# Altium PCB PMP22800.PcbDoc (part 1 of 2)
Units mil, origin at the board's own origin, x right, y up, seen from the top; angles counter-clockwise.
Board outline 4251.97 x 3450 mil, 2 copper layers (Top Layer, Bottom Layer), stack 62 mil thick; 97 components, 47 nets, 286 pads, 121 vias.
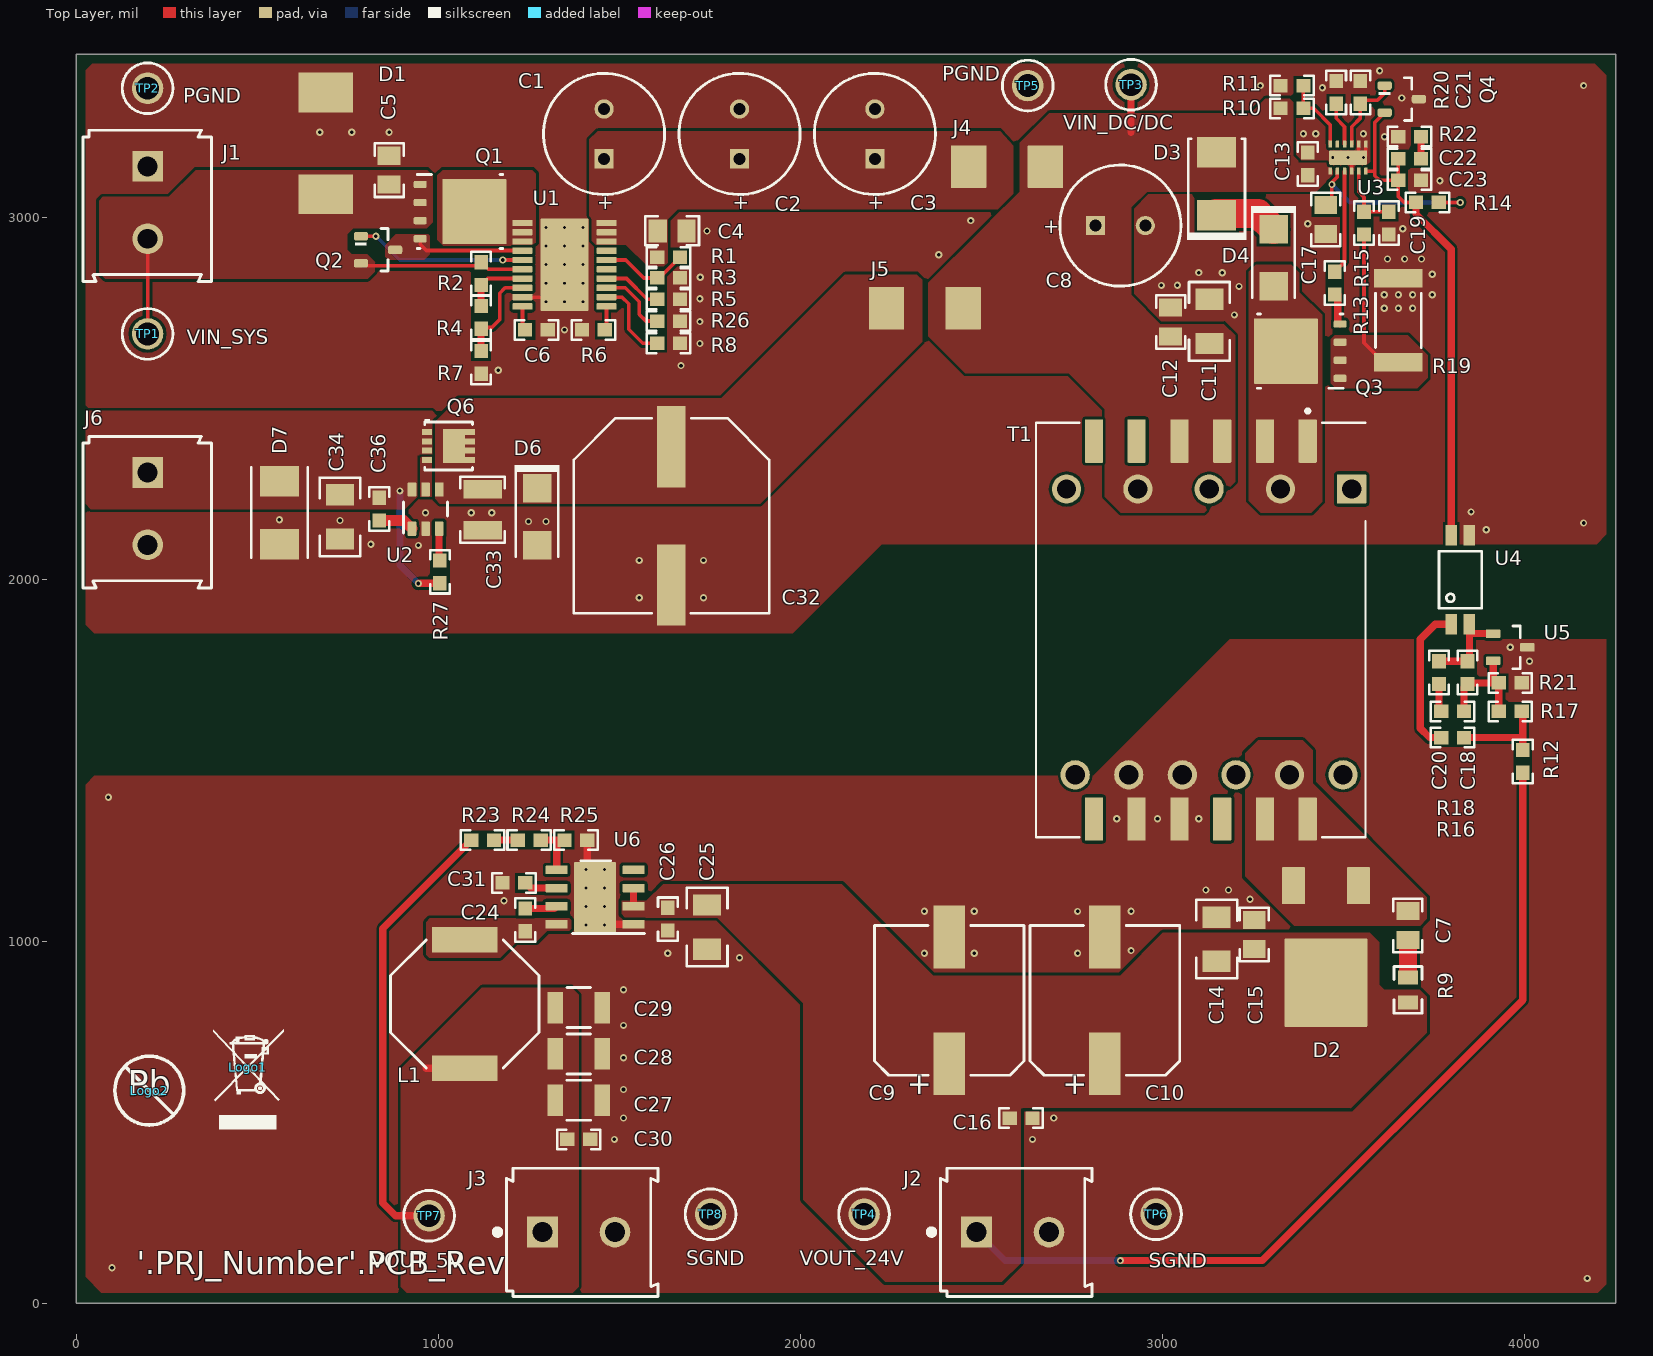
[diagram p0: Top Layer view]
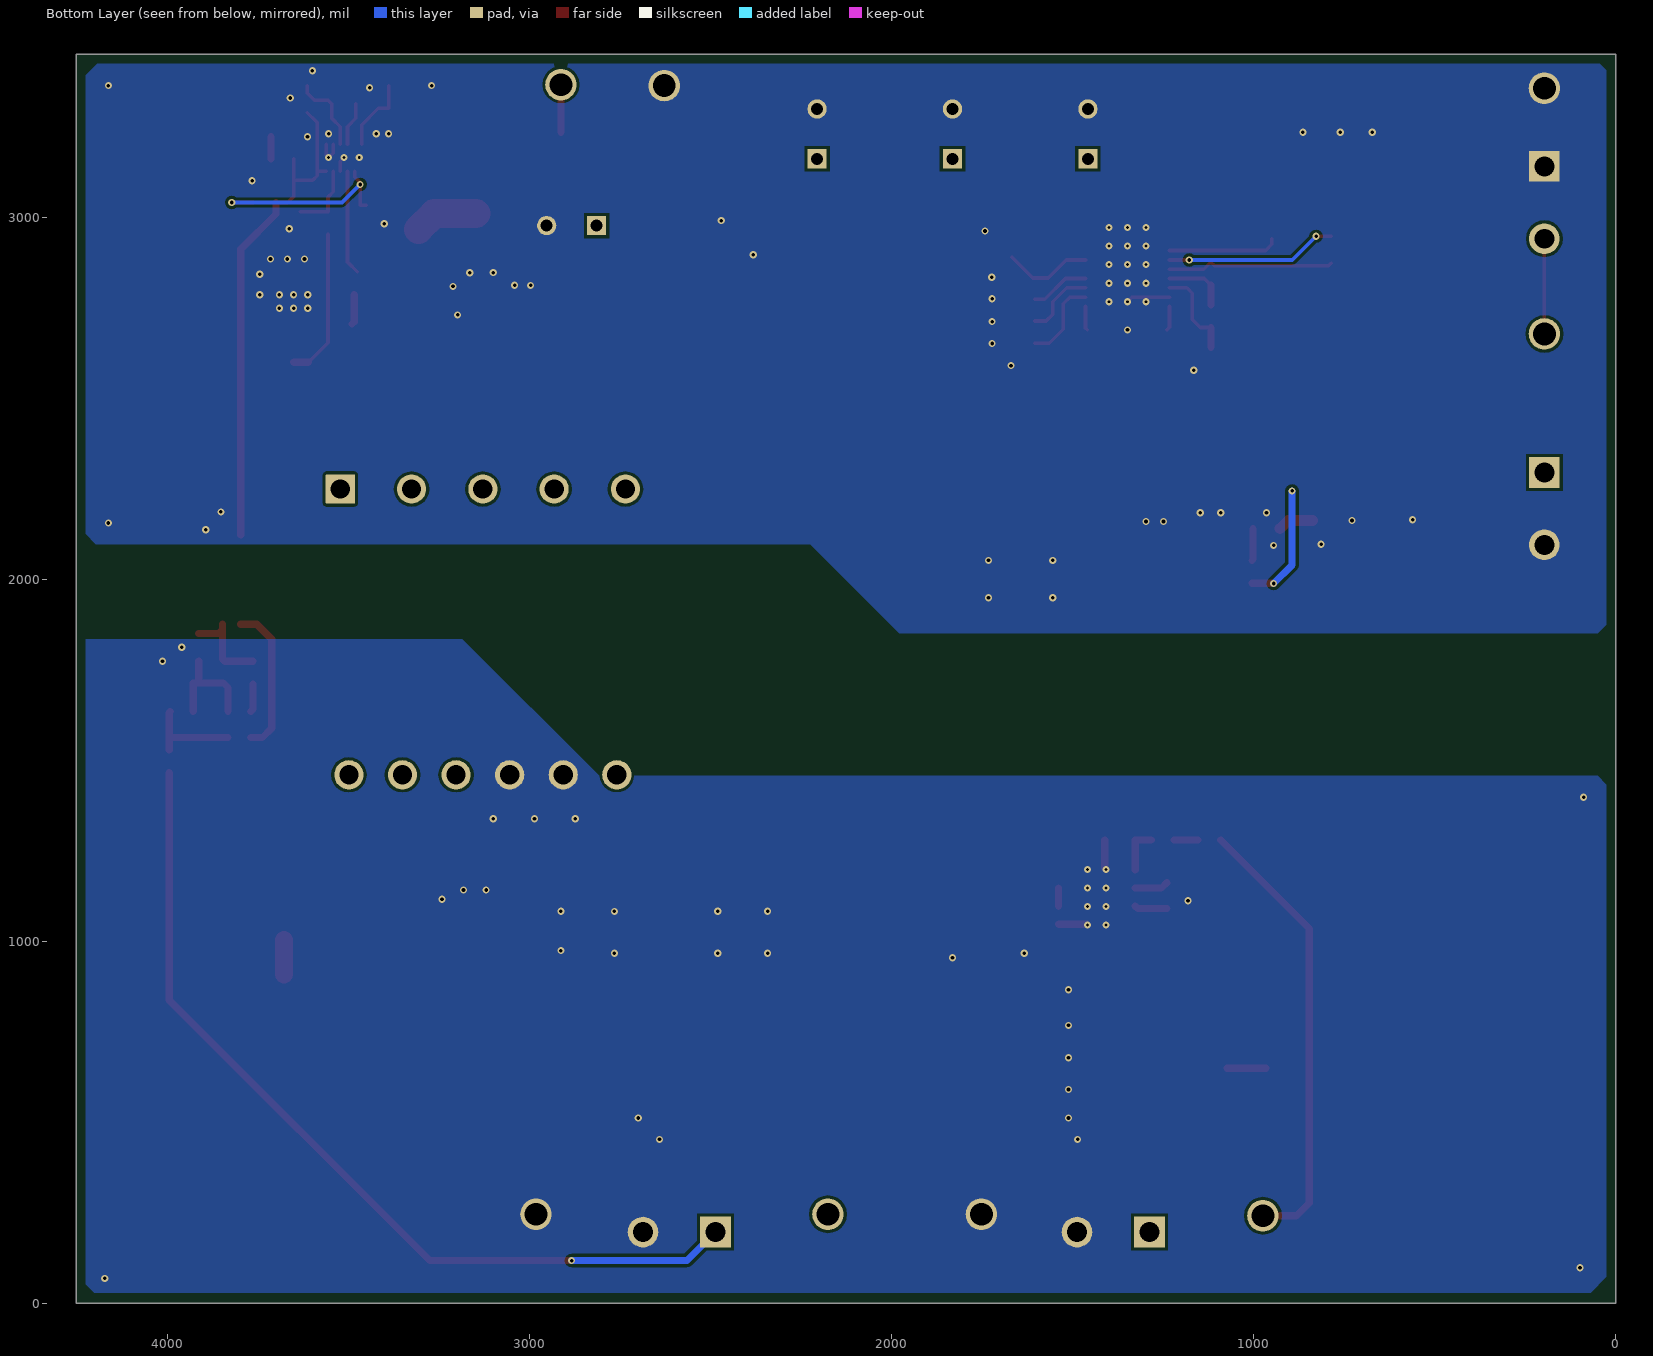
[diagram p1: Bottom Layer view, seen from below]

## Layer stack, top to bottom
Top Solder: solder mask 0.4, Solder Resist, Dk 3.5
Top Layer: signal copper 1.4
Dielectric1: core 59.2, FR-4, Dk 4.8
Bottom Layer: signal copper 1.4
Bottom Solder: solder mask 0.4, Solder Resist, Dk 3.5

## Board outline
0,0 4251.97,0 4251.97,3450 0,3450

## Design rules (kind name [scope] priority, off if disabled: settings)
AcuteAngle [All] p1: minimum=4.50000000000000E+0001 checktracksonly=FALSE
AssemblyTestPointUsage [All] p1: valid=2
BoardOutlineClearance BoardOutlineClearance_MountingHoles [OnCopper and InComponentClass('Mounting Holes')] p1: gap=25 ignorepadtopadclearanceinfootprint=FALSE
BoardOutlineClearance BoardOutlineClearance_Poly [OnCopper and InPoly] p2: gap=25 ignorepadtopadclearanceinfootprint=FALSE
BoardOutlineClearance [OnCopper and Not InComponentClass('Logo') and not InComponentClass('FiducialMark') and not InRegion(1000,500,4000,800)] p3: gap=25 ignorepadtopadclearanceinfootprint=FALSE
Clearance Clearance_Keepouts [((IsTrack Or IsArc) And Not InPoly) And IsFree and IsKeepOut vs ((IsTrack Or IsArc) And Not InPoly) And IsFree and IsKeepOut] p1: gap=0 ignorepadtopadclearanceinfootprint=FALSE
Clearance Clearance_Poly [InPolygon] p2: gap=8 ignorepadtopadclearanceinfootprint=FALSE except(0: Arc-Hole Track-Hole SMDPad-Hole THPad-Hole Via-Hole Fill-Hole Poly-Hole Region-Hole Text-Hole)
Clearance Clearance_FiducialMark [IsKeepOut and InComponentClass('FiducialMark') vs IsPad and InComponentClass('FiducialMark')] p3: gap=0 ignorepadtopadclearanceinfootprint=FALSE
Clearance [All] p4: gap=7.87 ignorepadtopadclearanceinfootprint=FALSE except(0: Arc-Hole Track-Hole SMDPad-Hole THPad-Hole Via-Hole Fill-Hole Poly-Hole Region-Hole Text-Hole)
ComponentClearance ComponentClearance_MountingHoles_FiducialMarks [InComponentClass('Mounting Holes') vs InComponentClass('FiducialMark')] p1: gap=50 collisioncheckmode=3 verticalgap=10 showdistances=FALSE
ComponentClearance ComponentClearance_Shunt [InComponentClass('Header') vs InComponentClass('Shunt')] p2: gap=0 collisioncheckmode=3 verticalgap=0 showdistances=FALSE
ComponentClearance ComponentClearance_Logo [InComponentClass('Logo')] p3: gap=50 collisioncheckmode=3 verticalgap=10 showdistances=FALSE
ComponentClearance ComponentClearance_ScrewToNut [(HasFootprint('NY PMS 440 0025 PH')) vs (HasFootprint('Keystone_1902C'))] p4: gap=5 collisioncheckmode=3 verticalgap=10 showdistances=FALSE
ComponentClearance ComponentClearance_MountingHoles [InComponentClass('Mounting Holes')] p5: gap=250 collisioncheckmode=3 verticalgap=100000 showdistances=FALSE
ComponentClearance ComponentClearance_SmallPassives [HasFootprint('0201*') or HasFootprint('0402*') or HasFootprint('0508') or HasFootprint('0603*') or HasFootprint('0612') or HasFootprint('0805*') or HasFootprint('0815*') or HasFootprint('0830*') or HasFootprint('1206*') or HasFootprint('1210*') or HasFootprint('1808*') or HasFootprint('1812*') or HasFootprint('1825*') or HasFootprint('2010*') or HasFootprint('2220*') or HasFootprint('2225*') or HasFootprint('2512*') or HasFootprint('2728*') or HasFootprint('3518*') vs HasFootprint('0201*') or HasFootprint('0402*') or HasFootprint('0508') or HasFootprint('0603*') or HasFootprint('0612') or HasFootprint('0805*') or HasFootprint('0815*') or HasFootprint('0830*') or HasFootprint('1206*') or HasFootprint('1210*') or HasFootprint('1808*') or HasFootprint('1812*') or HasFootprint('1825*') or HasFootprint('2010*') or HasFootprint('2220*') or HasFootprint('2225*') or HasFootprint('2512*') or HasFootprint('2728*') or HasFootprint('3518*')] p6: gap=14.96 collisioncheckmode=3 verticalgap=10 showdistances=FALSE
ComponentClearance ComponentClearance_THtoSMT [IsThruComponent vs IsSMTComponent] p7: gap=15 collisioncheckmode=3 verticalgap=30 showdistances=FALSE
ComponentClearance ComponentClearance_THtoTH [IsThruComponent vs IsThruComponent] p8: gap=15 collisioncheckmode=3 verticalgap=30 showdistances=FALSE
ComponentClearance [All] p9: gap=15 collisioncheckmode=3 verticalgap=10 showdistances=FALSE
DiffPairsRouting [All] p1: maxlimit=100 minlimit=10 mostfreqgap=10 toplayer_minwidth=15 toplayer_maxwidth=15 toplayer_prefwidth=15 bottomlayer_minwidth=15 bottomlayer_maxwidth=15 bottomlayer_prefwidth=15 maxuncoupledlength=1000
FabricationTestPointUsage TestPointUsage [All] p1: valid=2 allowmultiple=FALSE
FabricationTestpoint Testpoint [All] p1: side=3 testpointundercomponent=TRUE minsize=40 maxsize=100 preferedsize=60 minholesize=0 maxholesize=40 preferedholesize=32 testpointgrid=1 allowsidetop=TRUE allowsidebottom=TRUE usegrid=TRUE gridtolerance=0.01
FanoutControl Fanout_LCC [IsLCC] p1: bgadir=Out bgaviamode=Centered fanoutstyle=Auto fanoutdirection=Alternating viagrid=1 // Fanout_LCC (Default Rule)
FanoutControl Fanout_BGA [IsBGA] p2: bgadir=Out bgaviamode=Centered fanoutstyle=Auto fanoutdirection=Alternating viagrid=1 // Fanout_BGA (Default Rule)
FanoutControl Fanout_Default [All] p4: bgadir=Out bgaviamode=Centered fanoutstyle=Auto fanoutdirection=Alternating viagrid=1 // Fanout_Default (Default Rule)
FanoutControl Fanout_Small [(CompPinCount < 5)] p5: bgadir=Out bgaviamode=Centered fanoutstyle=Auto fanoutdirection=OutThenIn viagrid=1 // Fanout_Small (Default Rule)
HoleSize [All] p1: absolutevalues=TRUE maxlimit=251 minlimit=7.87 maxpercent=80.000 minpercent=20.000
MinimumAnnularRing MinimumAnnularRing_ThermalPadVias [IsVia and InAnyComponent] p1: minimumring=5
MinimumAnnularRing [All] p2: minimumring=5
MinimumSolderMaskSliver MinimumSolderMaskSliver_Logo [InComponentClass('Logo') vs InComponentClass('Logo')] p1: minsoldermaskwidth=0.7
MinimumSolderMaskSliver [All] p2: minsoldermaskwidth=3.94
PlaneConnect [All] p1: planeconnectstyle=Direct reliefexpansion=10 reliefentries=4 reliefconductorwidth=10 reliefairgap=10
PolygonConnect [All] p1: connectstyle=Direct reliefconductorwidth=10 reliefentries=4 polygonreliefangle="90 Angle" airgapwidth=10
RoutingVias ThermalPadVias [IsVia and InAnyComponent] p1: holewidth=7.87 width=19.68 viastyle="Through Hole" minholewidth=7.87 minwidth=19.68 maxholewidth=12.99 maxwidth=23.62
RoutingVias [All] p2: holewidth=16 width=34 viastyle="Through Hole" minholewidth=5 minwidth=10 maxholewidth=40 maxwidth=65
SilkToBoardRegionClearance [Not ((IsComment or IsDesignator) And (Hide <> 'False')) and not InRegion(1000,500,4000,800)] p1:
SilkToSilkClearance SilkToSilkClearance_Pb-FreeLogo [(HasFootprint('Pb-Free_Overlay_Medium') OR HasFootprint('Pb-Free_Overlay_Small')) vs (HasFootprint('Pb-Free_Overlay_Medium') OR HasFootprint('Pb-Free_Overlay_Small'))] p1: silktosilkclearance=0
SilkToSilkClearance [All] p2: silktosilkclearance=4
SilkToSolderMaskClearance SilkToComponentPadClearance [IsPad and InAnycomponent] p1: minsilkscreentomaskgap=5 clearancetoexposedcopper=TRUE
SilkToSolderMaskClearance "Silk to Solder Mask Opening" [All] p2: minsilkscreentomaskgap=4 clearancetoexposedcopper=FALSE
SolderMaskExpansion [All] p1: expansion=1.97
Width [All] p1: maxlimit=100 minlimit=6 preferedwidth=10 checkconnectedcopper=TRUE
15 further rules are at their usual default settings.

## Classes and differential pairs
component class PMP22800_Protection: !PCB1 C1 C2 C3 C4 C5 C6 C32 C33 C34 C36 D1 D6 D7 J1 J4 J5 J6 Logo1 Logo2 Q1 Q2 Q6 R1 R2 R3 R4 R5 R6 R7 R8 R26 R27 TP1 TP2 U1 U2
component class PMP22800_Power: C7 C8 C9 C10 C11 C12 C13 C14 C15 C16 C17 C18 C19 C20 C21 C22 C23 C24 C25 C26 C27 C28 C29 C30 C31 D2 D3 D4 J2 J3 L1 Q3 Q4 R9 R10 R11 R12 R13 R14 R15 R16 R17 R18 R19 R20 R21 R22 R23 R24 R25 T1 TP3 TP4 TP5 TP6 TP7 TP8 U3 U4 U5 U6

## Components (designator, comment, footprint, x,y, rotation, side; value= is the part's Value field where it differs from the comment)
C1 "EKZN350ELL221MH15D" KZN_800x1500 1457.77,3230.17 r90 top value=220uF
C2 "EKZN350ELL221MH15D" KZN_800x1500 1831.78,3230.17 r90 top value=220uF
C3 "EKZN350ELL221MH15D" KZN_800x1500 2205.8,3230.17 r90 top value=220uF
C4 "GJ821BR71H105KA12L" 0805_HV 1645.93,2962.24 r0 top value=1uF
C5 "GJ821BR71H105KA12L" 0805_HV 863.88,3129.92 r90 top value=1uF
C6 "C0603C223K3RACTU" 0603 1270.76,2688.83 r0 top value=0.022uF
C7 "C2012X7R2E102K085AA" 0805_HV 3678.15,1043.31 r90 top value=1000pF
C8 "EKZN350ELL221MH15D" KZN_800x1500 2883.86,2976.92 r0 top value=220uF
C9 "HHXB500ARA101MJA0G" HXB_JA0 2411.42,836.61 r90 top value=100uF
C10 "HHXB500ARA101MJA0G" HXB_JA0 2841.04,836.61 r90 top value=100uF
C11 "CL31B106KBHNNNE" 1206_180M 3129.92,2712.38 r90 top value=10uF
C12 "CL21B105KBFNFNE" 0805_HV 3022.72,2710.69 r90 top value=1uF
C13 "06035C104JAT2A" 0603 3401.38,3147.18 r90 top value=0.1uF
C14 "CL31B106KBHNNNE" 1206_180M 3149.61,1005.91 r90 top value=10uF
C15 "CL21B105KBFNFNE" 0805_HV 3253.67,1018.35 r90 top value=1uF
C16 "06035C104JAT2A" 0603 2609.68,511.81 r0 top value=0.1uF
C17 "C2012X7R1E475K125AB" 0805_HV 3451.25,2993.54 r90 top value=4.7uF
C18 "C0603C103K5RACTU" 0603 3842.72,1742.13 r90 top value=0.01uF
C19 "C0603C331K5RACTU" 0603 3625.68,2983.7 r90 top value=330pF
C20 "06035C104JAT2A" 0603 3763.98,1742.13 r90 top value=0.1uF
C21 "GRM188R71E103KA01D" 0603 3546.94,3344.98 r90 top value=0.01uF
C22 "C0603X104K3RACTU" 0603 3682.77,3161.72 r0 top value=0.1uF
C23 "C0603C331K5RACTU" 0603 3682.77,3102.66 r0 top value=330pF
C24 "C0603X104K3RACTU" 0603 1240.16,1059.06 r270 top value=0.1uF
C25 "C3216X7R1H475K160AE" 1206_190M 1742.13,1039.37 r270 top value=4.7uF
C26 "C1608X7R1H224K080AB" 0603 1633.86,1061.02 r270 top value=0.22uF
C27 "C3225X7R1C226K250AC" 1210_280 1387.8,561.02 r0 top value=22uF
C28 "C3225X7R1C226K250AC" 1210_280 1387.8,688.98 r0 top value=22uF
C29 "C3225X7R1C226K250AC" 1210_280 1387.8,816.93 r0 top value=22uF
C30 "C0603C104J4RACTU" 0603 1387.8,452.76 r180 top value=0.1uF
C31 "CL10B105KO8NFNC" 0603 1208.66,1161.42 r180 top value=1uF
C32 "EEV-FK1J221Q" SM_RADIAL_H13 1643.7,2175.2 r270 top value=220uF
C33 "C1210C225K1RACTU" 1210_210 1122.24,2191.93 r270 top value=2.2uF
C34 "CGA5L2X8R1H334K160AA" 1206_180M 728.35,2172.24 r270 top value=0.33uF
C36 "CGA3E1X7R1E105K080AD" 0603 836.61,2193.9 r270 top value=1uF
D1 "SMCJ33CA-13-F" SMC_Bi 688.98,3203.92 r270 top value=33V
D2 "VS-50WQ10FNTRHM3" DPAK 3451.77,1019.69 r270 top value=100V
D3 "SMBJ30A-13-F" SMB 3149.61,3092.22 r90 top value=30V
D4 "ES1C-13-F" SMA 3307.09,2887.73 r270 top value=150V
D6 "SMAJ58A" SMA 1272.64,2172.24 r270 top value=58V
D7 "SMBJ33CA-13-F" SMB-Bi 561.02,2184.06 r90 top value=33V
J1 "282841-2" TEC_282841-2 196.85,3040.61 r270 top
J2 "282841-2" TEC_282841-2 2586.61,196.85 r0 top
J3 "282841-2" TEC_282841-2 1387.8,196.85 r0 top
J4 "5102" Keystone_5102 2570.77,3139.57 r0 top
J5 "5102" Keystone_5102 2343.77,2748.82 r0 top
J6 "282841-2" TEC_282841-2 196.85,2194.88 r270 top
L1 "744066180" WE-TPC_1038 1072.83,826.77 r270 top value=18uH
Logo1 "WEEE logo" WEEE_Minimum 473.23,652.42 r0 top
Logo2 "Pb-Free Symbol" Pb-Free_Overlay_Medium 201.53,587.75 r0 top
Q1 "CSD19533Q5A" DQJ0008A 1059.84,3015.61 r0 top value=100V
Q2 "RK7002BMT116" SOT-23_Rohm 833.37,2910.1 r0 top value=60V
Q3 "CSD19533Q5A" DQJ0008A 3380.71,2629.92 r180 top value=100V
Q4 "FMMT718TA" SOT-23 3661.12,3326.28 r0 top value="20 V"
Q6 "DMT6007LFG-13" PowerDI3333-8 1028.2,2368.11 r0 top value=60V
R1 "RC0603FR-07499KL" 0603 1636.08,2889.86 r180 top value=499k
R2 "RC0603FR-07453KL" 0603 1118.11,2844.23 r90 top value=453k
R3 "RC0603FR-0782K5L" 0603 1636.08,2832.32 r180 top value=82.5k
R4 "RC0603FR-0760K4L" 0603 1118.11,2723.29 r90 top value=60.4k
R5 "RC0603FR-0722K6L" 0603 1636.08,2773.26 r0 top value=22.6k
R6 "RC0603FR-073K01L" 0603 1428.24,2688.83 r180 top value=3.01k
R7 "RC0603FR-0720KL" 0603 1118.11,2599.15 r90 top value=20.0k
R8 "RMCF0603ZT0R00" 0603 1636.08,2652.08 r180 top value=0
R9 "5106" 5106 3678.15,866.14 r270 top value=0
R10 "CRCW06031M40FKEA" 0603 3357.97,3300.69 r180 top value=1.40Meg
R11 "RC0603FR-07150KL" 0603 3357.97,3363.68 r0 top value=150k
R12 "RMCF0603ZT0R00" 0603 3995.28,1497.05 r270 top value=0
R13 "RMCF0603ZT0R00" 0603 3475.92,2817.85 r270 top value=0
R14 "RC0603FR-073K3L" 0603 3731.98,3040.88 r180 top value=3.30k
R15 "RC0603FR-072K49L" 0603 3556.79,2983.7 r270 top value=2.49k
R16 "RC0603FR-078K25L" 0603 3801.57,1562.65 r0 top value=8.25k
R17 "RC0603FR-07100KL" 0603 3960.83,1634.84 r0 top value=100k
R18 "ERJ-P03F3011V" 0603 3801.38,1634.84 r180 top value=3.01k
R19 "PMR100HZPFU7L00" 2512 3651.92,2715.29 r270 top value=0.007
R20 "RC0603FR-07220KL" 0603 3479.79,3344.98 r270 top value=220k
R21 "RC0603FR-0711K5L" 0603 3960.83,1713.58 r180 top value=11.5k
R22 "ERJ-P03F3011V" 0603 3682.77,3222.6 r0 top value=3.01k
R23 "RMCF0603ZT0R00" 0603 1122.24,1279.53 r180 top value=0
R24 "RC0603FR-07100KL" 0603 1250.98,1279.53 r0 top value=100k
R25 "RC0603FR-0724K9L" 0603 1379.92,1279.53 r180 top value=24.9k
R26 "RMCF0603ZT0R00" 0603 1636.08,2713.3 r180 top value=0
R27 "RMCF0603ZT0R00" 0603 1004.43,2020.67 r270 top value=0
T1 "750311604" FP-750311604_SMT_XFRMR_29MM08_23MM11-MFG 3106.1,1859.84 r270 top
TP1 "VIN_SYS" Keystone5010 196.85,2677.86 r0 top
TP2 "PGND" Keystone5011 196.85,3356.3 r0 top
TP3 "VIN_DC/DC" Keystone5010 2913.39,3366.14 r90 top
TP4 "VOUT_24V" Keystone5010 2175.83,246.06 r180 top
TP5 "PGND" Keystone5011 2627.95,3363.68 r0 top
TP6 "SGND" Keystone5011 2982.28,246.06 r0 top
TP7 "VOUT_5V" Keystone5010 974.41,241.84 r180 top
TP8 "SGND" Keystone5011 1751.97,246.06 r180 top
U1 "TPS26631PWPR" PWP0020T_N 1348.43,2869.03 r0 top
U2 "LM74700QDBVTQ1" DBV0006A_N 964.57,2193.9 r90 top
U3 "LM5155DSSR" DSS0012B 3512.89,3164.67 r90 top
U4 "PS2811-1-M-A" PS2811-1 3823.03,1999.02 r90 top
U5 "TL431LIAIDBZR" DBZ0003A_N 3960.83,1812.01 r0 top
U6 "LMR33620ADDAR" DDA0008J 1433.07,1122.05 r180 top

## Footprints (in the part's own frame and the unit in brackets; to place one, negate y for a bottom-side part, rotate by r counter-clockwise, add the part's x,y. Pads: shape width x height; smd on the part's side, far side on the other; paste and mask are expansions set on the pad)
0603 [mm] "0603 from SM-752 data"
  rect 1x0.95 smd: 1(-0.8,0) 2(0.8,0)
  silkscreen extent -1.52,-0.69 1.52,0.69, body extent -0.87,-0.47 0.87,0.47, height 1
0805_HV [mil] "0805 with 30mil clearance between pads"
  rect 50x63 smd: 1(-40,0) 2(40,0)
  silkscreen extent -74,-40 74,40, body extent -43,-29 43,29, height 57
1206_180M [mm] "1206_180"
  rect 1.5x1.95 smd: 1(-1.55,0) 2(1.55,0)
  silkscreen extent -2.76,-1.44 2.76,1.44, body extent -1.75,-0.95 1.75,0.95, height 1.8
1206_190M [mm] "1206_190"
  rect 1.5x1.95 smd: 1(-1.55,0) 2(1.55,0)
  silkscreen extent -2.76,-1.44 2.76,1.44, body extent -1.75,-0.95 1.75,0.95, height 1.9
1210_210 [mm] "1210"
  rect 1.3x2.7 smd: 1(-1.45,0) 2(1.45,0)
  silkscreen extent -2.32,-1.57 2.32,1.57, body extent -1.7,-1.35 1.7,1.35, height 2.1
1210_280 [mm] "SMD, 2-Leads, Body 3.6x2.8mm, Height 2.8mm"
  rect 1.1x2.2 smd: 1(-1.65,0) 2(1.65,0)
  silkscreen extent -0.84,-1.4 0.84,1.4, body extent -1.8,-1.4 1.8,1.4, height 2.8
2512 [mm] "Chip Resistor, Body 6.3x3.2mm, IPC Medium Density"
  rect 1.3x3.4 smd: 1(-2.95,0) 2(2.95,0)
  silkscreen extent -1.9,-1.6 1.9,1.6, body extent -3.22,-1.67 3.22,1.67, height 0.71
5106 [mm] "Keystone"
  rect 0.99x1.4 smd: 1(-0.85,0) 2(0.88,0)
  silkscreen extent -1.63,-0.97 1.65,0.97, body extent -1.06,-0.69 1.06,0.69, height 0.84
DBV0006A_N [mm] "SOT23, 6-Leads, Body 2.9x1.6mm, Pitch 0.95mm, Lead Span 2.8mm, IPC Medium Density"
  rrect17% 1x0.6 smd: 1(-1.375,0.95) 2(-1.375,0) 3(-1.375,-0.95) 4(1.375,-0.95) 5(1.375,0) 6(1.375,0.95)
  silkscreen extent -1.68,-1.55 0.5,1.55, body extent -1.42,-1.46 1.42,1.46, height 1.12
DBZ0003A_N [mm] "SOT23, 3-Leads, Body 2.9x1.3mm, Pitch 0.95mm, Lead Span 2.4mm, IPC Medium Density"
  rrect17% 1x0.6 smd: 1(-1.2,0.95) 2(-1.2,-0.95) 3(1.2,0)
  silkscreen extent 0.2,-1.5 0.7,1.5, body extent -1.26,-1.46 1.26,1.46, height 0.98
DDA0008J [mm] "SOIC, 8-Leads, Body 4.9x3.9mm, Pitch 1.27mm, Exposed Pad"
  rrect14% 1.55x0.6 smd: 1(-2.7,1.905) 2(-2.7,0.635) 3(-2.7,-0.635) 4(-2.7,-1.905) 5(2.7,-1.905) 6(2.7,-0.635) 7(2.7,0.635) 8(2.7,1.905)
  rrect4% 2.95x4.9 smd paste-1.5 mask-1.5: 9(0,0)
  silkscreen extent -3.47,-2.55 1.58,2.55, body extent -3.01,-2.45 3.01,2.45, height 1.57
DPAK [mm] "D-PAK, 3-Pads, Body 6.22x6.73mm (max), TO-252AA using nominal STEP model"
  rrect6% 2.6x1.6 smd: 1(-3.4,2.28) 3(-3.4,-2.28)
  rrect2% 6.2x5.8 smd paste-3: 2(3.4,0)
  body extent -3.86,-3.29 5.84,3.29, height 2.48
DQJ0008A [mm] "SMD, 8-Leads, Body 5.75x4.9mm"
  rrect39% 0.91x0.51 smd paste-0.05 mask-0.05: 1(-2.795,1.905) 2(-2.795,0.635) 3(-2.795,-0.635) 4(-2.795,-1.905) 5(2.795,-1.905) 6(2.795,-0.635) 7(2.795,0.635) 8(2.795,1.905)
  rrect8% 1.58x1.25 on Top Paste: 9(-0.38,-1.45) 9(-0.38,0) 9(-0.38,1.45) 9(1.4,-1.45) 9(1.4,0) 9(1.4,1.45)
  rrect3% 3.48x4.47 on Top Solder: 9(0.55,0)
  rrect2% 4.49x4.57 smd paste-2.5 mask-2.5: 9(1.005,0)
  silkscreen extent -3,-2.6 3,2.6, body extent -3.13,-2.45 3.13,2.45, height 1.15
DSS0012B [mm] "WSON-10"
  rrect40% 0.5x0.25 smd: 1(-0.95,1.25) 2(-0.95,0.75) 3(-0.95,0.25) 4(-0.95,-0.25) 5(-0.95,-0.75) 6(-0.95,-1.25) 7(0.95,-1.25) 8(0.95,-0.75) 9(0.95,-0.25) 10(0.95,0.25) 11(0.95,0.75) 12(0.95,1.25)
  rrect11% 1x2.65 smd paste-0.5: 13(0,0)
  body extent -1,-1.5 1,1.5, height 0.81
FP-750311604_SMT_XFRMR_29MM08_23MM11-MFG [mm]
  rrect8% 3.05x1.27 smd paste+0 mask+0: 1(-13.26,7.5) 2(-13.26,4.5) 3(-13.26,1.5) 4(-13.26,-1.5) 5(-13.26,-4.5) 6(-13.26,-7.5) 7(13.26,-7.5) 8(13.26,-4.5) 9(13.26,-1.5) 10(13.26,1.5) 11(13.26,4.5) 12(13.26,7.5)
  silkscreen extent -15.49,-11.56 14.54,11.56, body extent -14.88,-11.66 14.88,11.66, height 0.25
HXB_JA0 [mm] "SMD, 2-Leads, Dia 10mm"
  rect 4.4x2.2 smd: 1(-4.45,0) 2(4.45,0)
  silkscreen extent -5.25,-5.25 5.25,5.25, body extent -5.25,-5.25 5.25,5.25, height 10.31
Keystone5010 [mil] "Keystone Multipurpose loops"
  round 87 hole 63: 1(0,0)
  silkscreen extent -70,-70 70,70, body extent -63,-63 63,62, height 319
Keystone5011 [mil] "Keystone Multipurpose loops"
  round 87 hole 63: 1(0,0)
  silkscreen extent -70,-70 70,70, body extent -63,-63 63,62, height 319
Keystone_5102 [mm] "Shorting Jumper, 5.375mm, 2 Position, SMT"
  rrect4% 2.475x3 smd: 1(-2.688,0) 2(2.688,0)
  body extent -3.42,-1.19 3.43,1.35, height 1
KZN_800x1500 [mm] "TH, 2-Leads, Dia 8mm, Pin Spacing 3.5mm"
  rect 1.35x1.35 hole 0.85: 1(-1.75,0)
  round 1.35 hole 0.85: 2(1.75,0)
  silkscreen extent -4.25,-4.25 4.25,4.25, body extent -4.22,-4.24 4.24,4.24, height 16.51
Pb-Free_Overlay_Medium [mil]
  silkscreen extent -95,-95 95,95
PowerDI3333-8 [mm] "SMD, 8-Leads, Body 3.3x3.3mm, Pitch 0.65mm"
  rect 0.7x0.42 smd: 1(-1.5,0.975) 2(-1.5,0.325) 3(-1.5,-0.325) 4(-1.5,-0.975) 5(1.5,-0.975) 6(1.5,-0.325) 7(1.5,0.325) 8(1.5,0.975)
  rect 1.55x2.37 smd: 9(0.375,0)
  silkscreen extent -1.68,-1.68 1.68,1.9, body extent -1.68,-1.68 1.68,1.68, height 0.86
PS2811-1 [mm] "NEC optocoupler"
  rect 1.45x0.8 smd: 1(-3.125,0.635) 2(-3.125,-0.635) 3(3.125,-0.635) 4(3.125,0.635)
  silkscreen extent -2,-1.5 2,1.5, body extent -2.2,-1.5 2.2,1.5, height 2.1
PWP0020T_N [mm] "HTSSOP-20, IPC Medium Density"
  rrect22% 1.4x0.45 smd: 1(-2.95,2.925) 2(-2.95,2.275) 3(-2.95,1.625) 4(-2.95,0.975) 5(-2.95,0.325) 6(-2.95,-0.325) 7(-2.95,-0.975) 8(-2.95,-1.625) 9(-2.95,-2.275) 10(-2.95,-2.925) 11(2.95,-2.925) 12(2.95,-2.275) 13(2.95,-1.625) 14(2.95,-0.975) 15(2.95,-0.325) 16(2.95,0.325) 17(2.95,0.975) 18(2.95,1.625) 19(2.95,2.275) 20(2.95,2.925)
  rrect6% 3.4x6.5 smd paste-2 mask-2: 21(0,0)
  body extent -3.2,-3.25 3.2,3.25, height 1.13
SM_RADIAL_H13 [mm] "12.5 x 13.5mm:  Panasonic H13"
  rect 5.7x2 smd: 1(-4.85,0) 2(4.85,0)
  silkscreen extent -6.85,-6.85 6.85,6.85, body extent -6.85,-6.85 6.85,6.85, height 14
SMA [mm] "Molded Diode, 2-Leads, Body 4.3x2.6mm, IPC Medium Density, based on OnSemi component dimensions and land pattern"
  rect 2x2 smd: 1(-2,0) 2(2,0)
  silkscreen extent -3.66,-1.57 2.79,1.57, body extent -2.6,-1.3 2.6,1.3, height 2.42
SMB [mil] "Molded Diode, 2-Leads, Body 5.4x3.6mm, IPC Medium Density, based on OnSemi component dimensions"
  rect 85x107.99 smd: 1(-87.01,0) 2(87.01,0)
  silkscreen extent -155,-82 125,82, body extent -106,-71 106,71, height 91
SMB-Bi [mil] "Molded Diode, 2-Leads, Body 5.4x3.6mm, IPC Medium Density, based on OnSemi component dimensions"
  rect 85x107.99 smd: 1(-87.01,0) 2(87.01,0)
  silkscreen extent -125,-79 125,79, body extent -104,-73 104,73, height 89
SMC_Bi [mil] "SMC, no polarity mark"
  rect 110x150 smd: 1(-140.49,0) 2(140.49,0)
  body extent -156,-116 156,116, height 92
SOT-23 [mm] "SOT23, 3-Leads, Body 2.9x1.3mm, Pitch 0.95mm, Lead Span 2.5mm, IPC Medium Density"
  rrect50% 1x0.6 smd: 1(-1.2,0.95) 2(-1.2,-0.95) 3(1.2,0)
  silkscreen extent -1.63,-1.5 0.7,1.5, body extent -1.16,-1.45 1.21,1.45, height 1
SOT-23_Rohm [mm] "SOT23, 3-Leads, Body 2.9x1.3mm, Pitch 0.95mm, Lead Span 2.5mm"
  rrect50% 1x0.6 smd: 1(-1.2,0.95) 2(-1.2,-0.95) 3(1.2,0)
  silkscreen extent -1.63,-1.5 0.7,1.5, body extent -1.16,-1.45 1.21,1.45, height 1
TEC_282841-2 [mm] "TE Connectivity"
  rect 2.15x2.15 hole 1.4: 1(-2.54,0)
  round 2.15 hole 1.4: 2(2.54,0)
  silkscreen extent -5.07,-4.52 5.55,4.47, body extent -5.08,-4.52 5.58,4.48, height 15.2
WE-TPC_1038 [mm] "WURTH"
  rect 1.8x4.6 smd: 1(-4.5,0) 2(4.5,0)
  silkscreen extent -4.5,-5.2 4.5,5.2, body extent -5.15,-5.15 5.15,5.15, height 4.1
WEEE_Minimum [mil] "WEEElie bin"
  silkscreen extent -95,-172 99,104

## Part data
C1 C2 C3 C8: library part CMP-0010431-2, "CAP, AL, 220 uF, 35 V, +/- 20%, 0.059 ohm, TH", Cap_Case=8x15mm, Manufacturer=Chemi-Con, Supplier Part Number 1=EKZN350ELL221MH15D-ND, Tolerance_%=20%, Value1="0.059 ohm", Value2=35V, ValueDisplayed=220uF
C4 C5: library part CMP-0750127-1, "CAP, CERM, 1 µF, 50 V,+/- 10%, X7R, 0805", Cap_Case=0805, Manufacturer=MuRata, TempCo=X7R, Tolerance_%=10%, Value2=50V, ValueDisplayed=1µF
C6: library part CMP-0006899-4, "CAP, CERM, 0.022 uF, 25 V, +/- 10%, X7R, 0603", Cap_Case=0603, Manufacturer=Kemet, Supplier Part Number 1=399-1094-1-ND, TempCo=X7R, Tolerance_%=10%, Value1=Unknown, Value2=25V, ValueDisplayed=0.022uF
C7: library part CMP-0064943-2, "CAP, CERM, 1000 pF, 250 V,+/- 10%, X7R, 0805", Cap_Case=0805, Manufacturer=TDK, Supplier Part Number 1=445-2277-1-ND, TempCo=X7R, Tolerance_%=10%, Value1=Unknown, Value2=250V, ValueDisplayed=1000pF
C9 C10: library part CMP-0012269-3, "CAP, Aluminum Polymer, 100 uF, 50 V, +/- 20%, 0.025 ohm, AEC-Q200 Grade 2, D10xL10mm SMD", Cap_Case=10x10mm, Manufacturer=Chemi-Con, Supplier Part Number 1=565-4187-1-ND, Tolerance_%=20%, Value1="0.025 ohm", Value2=50V, ValueDisplayed=100uF
C11 C14: library part CMP-0008802-2, "CAP, CERM, 10 uF, 50 V, +/- 10%, X7R, 1206", Cap_Case=1206, Manufacturer=Samsung, Supplier Part Number 1=1276-6767-1-ND, TempCo=X7R, Tolerance_%=10%, Value1=Unknown, Value2=50V, ValueDisplayed=10uF
C12 C15: library part CMP-0080611-1, "CAP, CERM, 1 µF, 50 V,+/- 10%, X7R, 0805", Cap_Case=0805, Manufacturer=Samsung, Supplier Part Number 1=1276-2928-1-ND, TempCo=X7R, Tolerance_%=10%, Value2=50V, ValueDisplayed=1µF
C13 C16 C20: library part CMP-0083854-1, "CAP, CERM, 0.1 µF, 50 V,+/- 5%, X7R, 0603", Cap_Case=0603, Manufacturer=AVX, TempCo=X7R, Tolerance_%=5%, Value2=50V, ValueDisplayed=0.1µF
C17: library part CMP-0007870-2, "CAP, CERM, 4.7 uF, 25 V, +/- 10%, X7R, 0805", Cap_Case=0805, Manufacturer=TDK, Supplier Part Number 1=445-5972-1-ND, TempCo=X7R, Tolerance_%=10%, Value1=Unknown, Value2=25V, ValueDisplayed=4.7uF
C18: library part CMP-0006854-4, "CAP, CERM, 0.01 uF, 50 V, +/- 10%, X7R, 0603", Cap_Case=0603, Manufacturer=Kemet, Supplier Part Number 1=399-1091-1-ND, TempCo=X7R, Tolerance_%=10%, Value1=Unknown, Value2=50V, ValueDisplayed=0.01uF
C19 C23: library part CMP-0006921-4, "CAP, CERM, 330 pF, 50 V, +/- 10%, X7R, 0603", Cap_Case=0603, Manufacturer=Kemet, Supplier Part Number 1=399-1073-1-ND, TempCo=X7R, Tolerance_%=10%, Value1=Unknown, Value2=50V, ValueDisplayed=330pF
C21: library part CMP-0007403-4, "CAP, CERM, 0.01 uF, 25 V, +/- 10%, X7R, 0603", Cap_Case=0603, Manufacturer=MuRata, Supplier Part Number 1=490-1520-1-ND, TempCo=X7R, Tolerance_%=10%, Value1=Unknown, Value2=25V, ValueDisplayed=0.01uF
C22 C24: library part CMP-0006979-5, "CAP, CERM, 0.1 uF, 25 V, +/- 10%, X7R, 0603", Cap_Case=0603, Manufacturer=Kemet, Supplier Part Number 1=399-5345-1-ND, TempCo=X7R, Tolerance_%=10%, Value1=Unknown, Value2=25V, ValueDisplayed=0.1uF
C25: library part CMP-0082522-1, "CAP, CERM, 4.7 µF, 50 V,+/- 10%, X7R, 1206", Cap_Case=1206, Manufacturer=TDK, Supplier Part Number 1=445-172491-1-ND, TempCo=X7R, Tolerance_%=10%, Value2=50V, ValueDisplayed=4.7µF
C26: library part CMP-0007047-4, "CAP, CERM, 0.22 uF, 50 V, +/- 10%, X7R, 0603", Cap_Case=0603, Manufacturer=TDK, Supplier Part Number 1=445-7408-1-ND, TempCo=X7R, Tolerance_%=10%, Value1="0.021699 ohm", Value2=50V, ValueDisplayed=0.22uF
C27 C28 C29: library part CMP-0009116-1, "CAP, CERM, 22 uF, 16 V, +/- 10%, X7R, 1210", Cap_Case=1210_280, Manufacturer=TDK, Supplier Part Number 1=445-3945-1-ND, TempCo=X7R, Tolerance_%=10%, Value1="0.002582 ohm", Value2=16V, ValueDisplayed=22uF
C30: library part CMP-0006857-4, "CAP, CERM, 0.1 uF, 16 V, +/- 5%, X7R, 0603", Cap_Case=0603, Manufacturer=Kemet, Supplier Part Number 1=399-1097-1-ND, TempCo=X7R, Tolerance_%=5%, Value1=Unknown, Value2=16V, ValueDisplayed=0.1uF
C31: library part CMP-0085537-1, "CAP, CERM, 1 µF, 16 V,+/- 10%, X7R, 0603", Cap_Case=0603, Manufacturer="Samsung Electro-Mechanics", TempCo=X7R, Tolerance_%=10%, Value2=16V, ValueDisplayed=1µF
C32: library part CMP-0011214-2, "CAP, AL, 220 uF, 63 V, +/- 20%, 0.16 ohm, AEC-Q200 Grade 2, SMD", Cap_Case=H13, Manufacturer=Panasonic, Supplier Part Number 1=PCE3484CT-ND, Tolerance_%=20%, Value1="0.16 ohm", Value2=63V, ValueDisplayed=220uF
C33: library part CMP-0009084-1, "CAP, CERM, 2.2 uF, 100 V, +/- 10%, X7R, 1210", Cap_Case=1210, Manufacturer=Kemet, Supplier Part Number 1=399-5511-2-ND, TempCo=X7R, Tolerance_%=10%, Value1=Unknown, Value2=100V, ValueDisplayed=2.2uF
C34: library part CMP-0078294-1, "CAP, CERM, 0.33 µF, 50 V,+/- 10%, X8R, AEC-Q200 Grade 0, 1206", Cap_Case=1206, Manufacturer=TDK, Supplier Part Number 1=445-5917-1-ND, TempCo=X8R, Tolerance_%=10%, Value2=50V, ValueDisplayed=0.33µF
C36: library part CMP-0082523-1, "CAP, CERM, 1 µF, 25 V,+/- 10%, X7R, AEC-Q200 Grade 1, 0603", Cap_Case=0603, Manufacturer=TDK, Supplier Part Number 1=445-9819-1-ND, TempCo=X7R, Tolerance_%=10%, Value2=25V, ValueDisplayed=1µF
D1: library part CMP-0086205-2, "Diode, TVS, Bi, 33 V, 53.3 Vc, 1500 W, 200 A, SMC", Manufacturer="Diodes Inc.", Value1=53.3V
D2: library part CMP-0028919-3, "Diode, Schottky, 100 V, 5.5 A, AEC-Q101, DPAK", Manufacturer=Vishay-Semiconductor, Value1=5.5A, Value2=0.77V
D3: library part CMP-0005561-4, "Diode, TVS, Uni, 30 V, 48.4 Vc, SMB", Manufacturer="Diodes Inc.", Value1=600W
D4: library part CMP-0029023-2, "Diode, Superfast Rectifier, 150 V, 1 A, SMA", Manufacturer="Diodes Inc.", Value1=1A, Value2=0.92V
D6: library part CMP-0005485-3, "Diode, TVS, Uni, 58 V, SMA", Manufacturer="Diodes Inc.", Value1=400W
D7: library part CMP-0005564-3, "Diode, TVS, Bi, 33 V, SMB", Manufacturer="Diodes Inc.", Value1=600W
J1 J2 J3 J6: library part CMP-0054973-1, "Terminal Block, 2x1, 5.08mm, TH", Manufacturer="TE Connectivity", Supplier Part Number 1=A98342-ND
J4 J5: library part CMP-0055135-1, "Shorting Jumper, 5.375mm, 2 Position, Tin, SMT", Color=Silver, Manufacturer=Keystone, Supplier Part Number 1=36-5102-ND
L1: library part CMP-0064445-2, "Inductor, Shielded, 18 uH, 2.8 A, 0.054 ohm, SMD", Manufacturer="Wurth Elektronik", Supplier Part Number 1=732-4096-6-ND, Value1="0.054 ohm", Value2=2.8A, ValueDisplayed=18uH
Logo1: library part CMP-0074769-1
Logo2: library part CMP-0074839-1
Q1 Q3: library part CMP-0000960-2, "MOSFET, N-CH, 100 V, 13 A, DQJ0008A (VSONP-8)", Alternate Manufacturer=None, Manufacturer="Texas Instruments", Supplier Part Number 1=CSD19533Q5A-ND, Value2="27 nC"
Q2: library part CMP-0000860-2, "MOSFET, N-CH, 60 V, 0.25 A, SOT-23", Alternate Manufacturer=None, Manufacturer=Rohm, Supplier Part Number 1=RK7002BMT116CT-ND
Q4: library part CMP-0000330-2, "Transistor, PNP, 20 V, 1.5 A, SOT-23", Manufacturer="Diodes Inc.", Supplier Part Number 1=FMMT718CT-ND, Value1="1.5 A", Value2=6
Q6: library part CMP-0067553-1, "MOSFET, N-CH, 60 V, 15 A, AEC-Q101, 8-PowerVDFN", Alternate Manufacturer=None, Manufacturer="Diodes Inc.", Supplier Part Number 1=DMT6007LFG-13-ND, Value1="0.0085 ohm", Value2="41.3 nC"
R1: library part CMP-0023140-4, "RES, 499 k, 1%, 0.1 W, 0603", Manufacturer=Yageo, Power_W=100mW, Supplier Part Number 1=311-499KHRCT-ND, TempCo="100 ppm/C", Tolerance_%=1%, Value2=0.1W, Value_Code=499k
R2: library part CMP-0023120-4, "RES, 453 k, 1%, 0.1 W, 0603", Manufacturer=Yageo, Power_W=100mW, Supplier Part Number 1=311-453KHRCT-ND, TempCo="100 ppm/C", Tolerance_%=1%, Value2=0.1W, Value_Code=453k
R3: library part CMP-0023291-5, "RES, 82.5 k, 1%, 0.1 W, 0603", Manufacturer=Yageo, Power_W=100mW, Supplier Part Number 1=311-82.5KHRCT-ND, TempCo="100 ppm/C", Tolerance_%=1%, Value2=0.1W, Value_Code=82k5, ValueDisplayed=82.5k
R4: library part CMP-0023212-5, "RES, 60.4 k, 1%, 0.1 W, 0603", Manufacturer=Yageo, Power_W=100mW, Supplier Part Number 1=311-60.4KHRCT-ND, TempCo="100 ppm/C", Tolerance_%=1%, Value2=0.1W, Value_Code=60k4, ValueDisplayed=60.4k
R5: library part CMP-0022924-5, "RES, 22.6 k, 1%, 0.1 W, 0603", Manufacturer=Yageo, Power_W=100mW, Supplier Part Number 1=311-22.6KHRCT-ND, TempCo="100 ppm/C", Tolerance_%=1%, Value2=0.1W, Value_Code=22k6, ValueDisplayed=22.6k
R6: library part CMP-0023076-5, "RES, 3.01 k, 1%, 0.1 W, 0603", Manufacturer=Yageo, Power_W=100mW, Supplier Part Number 1=311-3.01KHRCT-ND, TempCo="100 ppm/C", Tolerance_%=1%, Value2=0.1W, Value_Code=3k01, ValueDisplayed=3.01k
R7: library part CMP-0022906-5, "RES, 20.0 k, 1%, 0.1 W, 0603", Manufacturer=Yageo, Power_W=100mW, Supplier Part Number 1=311-20.0KHRCT-ND, TempCo="100 ppm/C", Tolerance_%=1%, Value2=0.1W, Value_Code=20k0, ValueDisplayed=20.0k
R8 R12 R13 R23 R26 R27: library part CMP-0023343-3, "RES, 0, 1%, 0.1 W, AEC-Q200 Grade 0, 0603", Manufacturer="Stackpole Electronics Inc", Power_W=100mW, Supplier Part Number 1=RMCF0603ZT0R00CT-ND, TempCo=ppm/C, Tolerance_%=1%, Value2=0.1W, Value_Code=0
R9: library part CMP-0020833-2, "RES, 0, 1%, 0.5 W, 0805", Manufacturer=Keystone, Power_W=500mW, Supplier Part Number 1=36-5106CT-ND, TempCo=ppm/C, Tolerance_%=1%, Value2=0.5W, Value_Code=0
R10: library part CMP-0022153-4, "RES, 1.40 M, 1%, 0.1 W, AEC-Q200 Grade 0, 0603", Manufacturer=Vishay-Dale, Power_W=100mW, Supplier Part Number 1=541-1.40MHCT-ND, TempCo="100 ppm/C", Tolerance_%=1%, Value2=0.1W, Value_Code=1M40, ValueDisplayed=1.40M
R11: library part CMP-0022808-4, "RES, 150 k, 1%, 0.1 W, 0603", Manufacturer=Yageo, Power_W=100mW, Supplier Part Number 1=311-150KHRCT-ND, TempCo="100 ppm/C", Tolerance_%=1%, Value2=0.1W, Value_Code=150k
R14: library part CMP-0023081-5, "RES, 3.30 k, 1%, 0.1 W, 0603", Manufacturer=Yageo, Power_W=100mW, Supplier Part Number 1=311-3.30KHRCT-ND, TempCo="100 ppm/C", Tolerance_%=1%, Value2=0.1W, Value_Code=3k30, ValueDisplayed=3.30k
R15: library part CMP-0022990-5, "RES, 2.49 k, 1%, 0.1 W, 0603", Manufacturer=Yageo, Power_W=100mW, Supplier Part Number 1=311-2.49KHRCT-ND, TempCo="100 ppm/C", Tolerance_%=1%, Value2=0.1W, Value_Code=2k49, ValueDisplayed=2.49k
R16: library part CMP-0023307-5, "RES, 8.25 k, 1%, 0.1 W, 0603", Manufacturer=Yageo, Power_W=100mW, Supplier Part Number 1=311-8.25KHRCT-ND, TempCo="100 ppm/C", Tolerance_%=1%, Value2=0.1W, Value_Code=8k25, ValueDisplayed=8.25k
R17 R24: library part CMP-0022735-5, "RES, 100 k, 1%, 0.1 W, 0603", Manufacturer=Yageo, Power_W=100mW, Supplier Part Number 1=311-100KHRCT-ND, TempCo="100 ppm/C", Tolerance_%=1%, Value2=0.1W, Value_Code=100k
R18 R22: library part CMP-0022729-3, "RES, 3.01 k, 1%, 0.2 W, 0603", Manufacturer=Panasonic, Power_W=200mW, Supplier Part Number 1=P16023CT-ND, TempCo="200 ppm/C", Tolerance_%=1%, Value2=0.2W, Value_Code=3k01, ValueDisplayed=3.01k
R19: library part CMP-0015839-2, "RES, 0.007, 1%, 2 W, 2512", Manufacturer=Rohm, Power_W=2W, Supplier Part Number 1=RHM.007AUCT-ND, TempCo="100 ppm/C", Tolerance_%=1%, Value_Code=7L000, ValueDisplayed=0.007
R20: library part CMP-0022917-4, "RES, 220 k, 1%, 0.1 W, 0603", Manufacturer=Yageo, Power_W=100mW, Supplier Part Number 1=311-220KHRCT-ND, TempCo="100 ppm/C", Tolerance_%=1%, Value2=0.1W, Value_Code=220k
R21: library part CMP-0022761-5, "RES, 11.5 k, 1%, 0.1 W, 0603", Manufacturer=Yageo, Power_W=100mW, Supplier Part Number 1=311-11.5KHRCT-ND, TempCo="100 ppm/C", Tolerance_%=1%, Value2=0.1W, Value_Code=11k5, ValueDisplayed=11.5k
R25: library part CMP-0022944-5, "RES, 24.9 k, 1%, 0.1 W, 0603", Manufacturer=Yageo, Power_W=100mW, Supplier Part Number 1=311-24.9KHRCT-ND, TempCo="100 ppm/C", Tolerance_%=1%, Value2=0.1W, Value_Code=24k9, ValueDisplayed=24.9k
T1: library part CMP-0091456-1, "Power Transformers WE-FB Flyback 8.0uH 1.3 24V", Digikey Part Number=732-2654-1-ND, Manufacturer="Wurth Electronics", Mouser Part Number=710-750311604, Operating Temperature Range="-40°C to +125°C", Voltage_Isolation_Vrms=1.5kV
TP1 TP3 TP4 TP7: library part CMP-0055147-1, "Test Point, Multipurpose, Red, TH", Color=Red, Manufacturer=Keystone, PartNumber=5010, Supplier Part Number 1=36-5010-ND
TP2 TP5 TP6 TP8: library part CMP-0055148-1, "Test Point, Multipurpose, Black, TH", Color=Black, Manufacturer=Keystone, PartNumber=5011, Supplier Part Number 1=36-5011-ND
U1: library part CMP-0860095-3, "60-V, 6-A Power limiting, surge protection industrial eFuse, PWP0020T (HTSSOP-20)", Alternate Manufacturer="Texas Instruments"
U2: library part CMP-0079180-1, "Low Iq Always ON Smart Diode Controller, DBV0006A (SOT-23-6)", Alternate Manufacturer="Texas Instruments", Alternate PartNumber=LM74700QDBVRQ1
U3: library part CMP-0085413-1, "2.2-MHz Wide Input Nonsynchronous Boost, Sepic, Flyback Controller, DSS0012B (WSON-12)", Alternate Manufacturer="Texas Instruments", Alternate PartNumber=LM5155DSST
U4: library part CMP-0006156-4, "Optocoupler, 2.5 kV, 100-200% CTR, SMT", Manufacturer="California Eastern Laboratories", Supplier Part Number 1=PS2811-1-M-A-ND, Voltage_Isolation_Vrms=2.5kV
U5: library part CMP-0084729-1, "Programmable Shunt Regulator with Optimized Reference Current, DBZ0003A (SOT-23-3)", Alternate Manufacturer="Texas Instruments"
U6: library part CMP-0074756-2, "3.8V to 36V 3A/2A Synchronous Step-Down Voltage Regulator, DDA0008J (SOIC-8)", Alternate Manufacturer="Texas Instruments", Alternate PartNumber=LMR33620ADDA

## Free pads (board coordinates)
  rect 23.62x9.45 on Mech1: 1(3508.9,2249.19)
  rrect5% 80.71x80.71 hole 53.15 paste-39370.1 mask+0: 1(3522.73,2249.19)
  round 80.71 hole 53.15 paste-39370.1 mask+0: 2(3129.03,2249.19) 2(3325.88,2249.19) 4(2932.18,2249.19) 5(2735.33,2249.19) 6(2758.95,1459.82) 7(2906.98,1459.82) 8(3055.01,1459.82) 9(3203.05,1459.82) 10(3351.08,1459.82) 11(3499.11,1459.82)

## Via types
v1: diameter 20, hole 10, Top Layer to Bottom Layer, 91 vias
v2: diameter 19.68, hole 7.87, Top Layer to Bottom Layer, 16 vias
v3: diameter 19.68, hole 7.87, Top Layer to Bottom Layer, tented both sides, 10 vias
v4: diameter 20, hole 10, Top Layer to Bottom Layer, tented top, 4 vias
